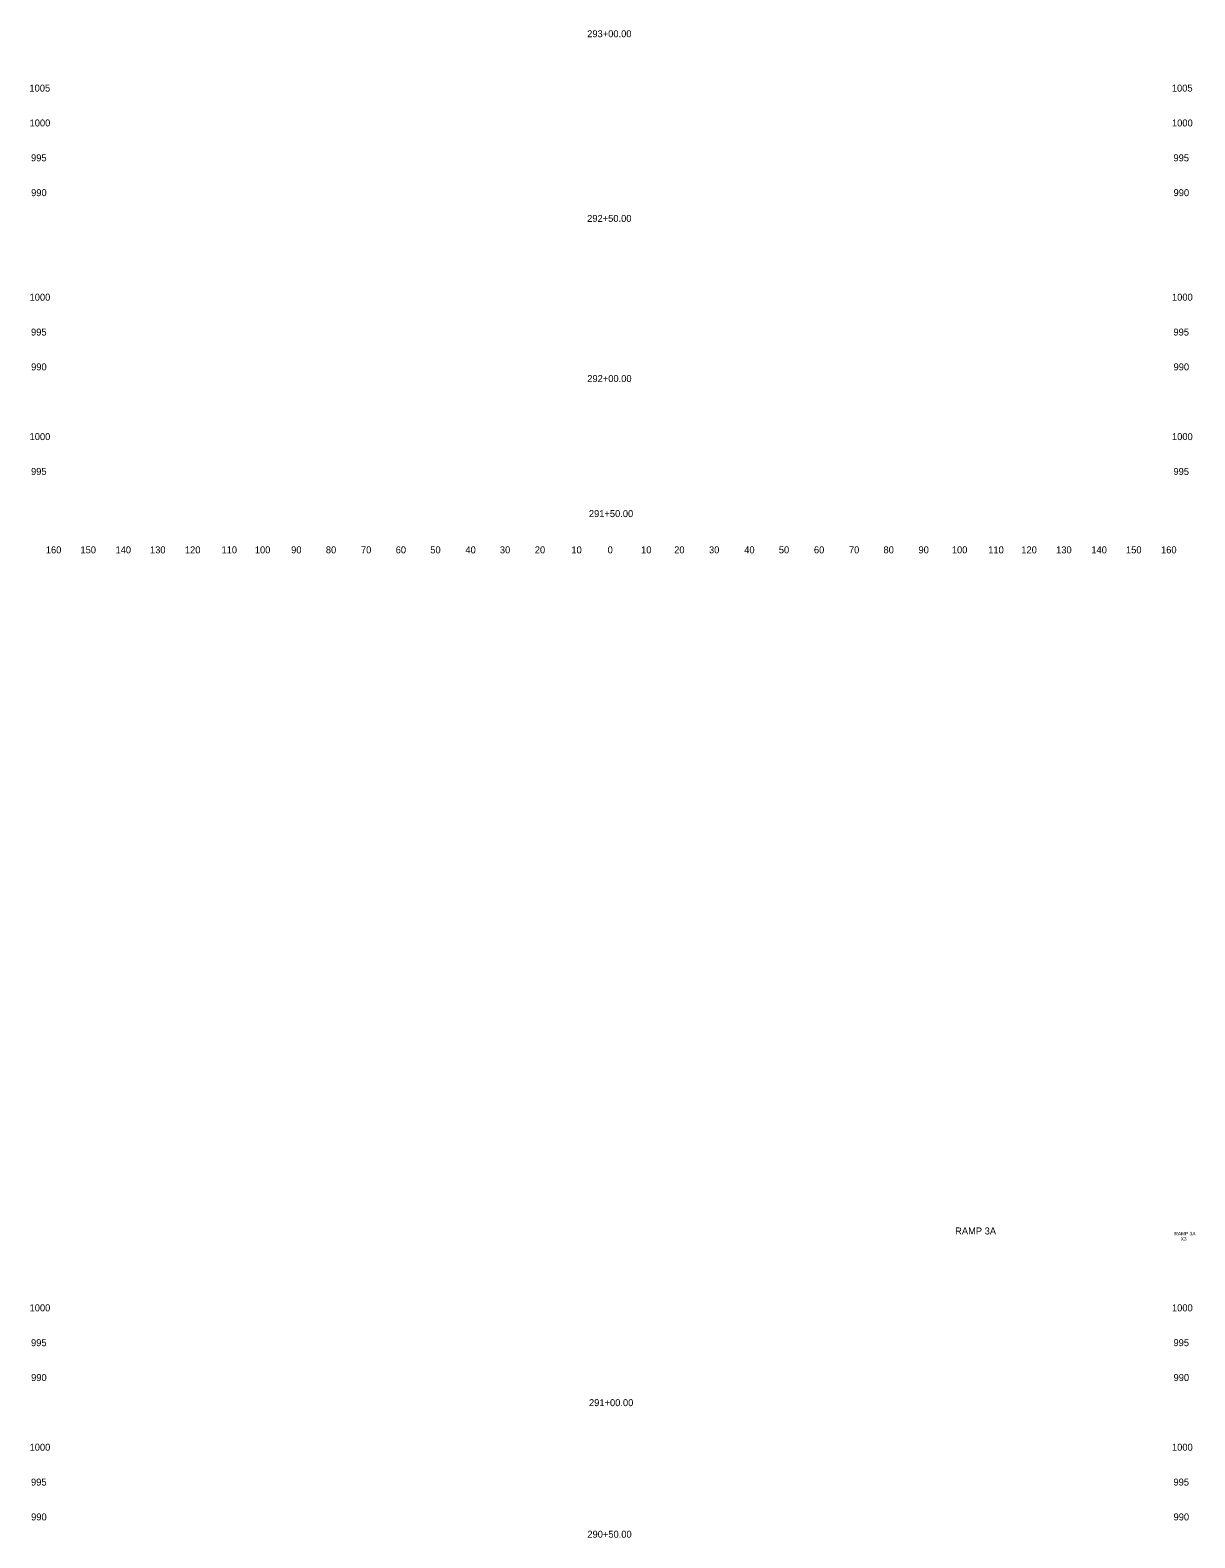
# Model space of a CAD drawing. Extents: x 4286 to 5843, y 4997 to 8804.
# Drawn here: x 4993.6 to 5327.8, y 5915 to 6347.6 of the extents above; entities that cross this region are included whole.
import ezdxf

# ---------------------------------------------------------------- set-up
doc = ezdxf.new("R2010")
doc.units = 0
for name, color, linetype in [('RD_SHT_ID', 7, 'Continuous'), ('RD_XS_TX_Offset', 7, 'Continuous'), ('RD_XS_TX_Station', 7, 'Continuous')]:
    doc.layers.add(name, color=color, linetype=linetype)

msp = doc.modelspace()

# ---------------------------------------------------------------- texts
at = {"layer": 'RD_SHT_ID'}
for s, height, p in [('RAMP 3A', 2, (5259.02, 6002.06)), ('RAMP 3A', 1, (5321.93, 6001.8)), ('X3', 1, (5323.74, 6000.3))]:
    msp.add_text(s, height=height, dxfattribs=at).set_placement(p)
at = {"layer": 'RD_XS_TX_Offset'}
for s, p in [('1005', (4993.4, 6330)), ('1005', (5321.2, 6330)), ('1000', (4993.44, 6320)), ('1000', (5321.24, 6320)), ('995', (4993.86, 6310)), ('995', (5321.66, 6310)), ('990', (4993.89, 6300)), ('990', (5321.69, 6300)), ('1000', (4993.44, 6270)), ('1000', (5321.24, 6270)), ('995', (4993.86, 6260)), ('995', (5321.66, 6260)), ('990', (4993.89, 6250)), ('990', (5321.69, 6250)), ('1000', (4993.44, 6230)), ('1000', (5321.24, 6230)), ('995', (4993.86, 6220)), ('995', (5321.66, 6220)), ('160', (4998.1, 6197.5)), ('150', (5008.04, 6197.5)), ('140', (5018.1, 6197.5)), ('130', (5027.99, 6197.5)), ('120', (5038.01, 6197.5)), ('110', (5048.51, 6197.5)), ('100', (5058.07, 6197.5)), ('90', (5068.5, 6197.5)), ('80', (5078.46, 6197.5)), ('70', (5088.54, 6197.5)), ('60', (5098.5, 6197.5)), ('50', (5108.43, 6197.5)), ('40', (5118.5, 6197.5)), ('30', (5128.39, 6197.5)), ('20', (5138.4, 6197.5)), ('10', (5148.91, 6197.5)), ('0', (5159.3, 6197.5)), ('0', (5159.3, 6197.5)), ('10', (5168.91, 6197.5)), ('20', (5178.4, 6197.5)), ('30', (5188.39, 6197.5)), ('40', (5198.5, 6197.5)), ('50', (5208.43, 6197.5)), ('60', (5218.5, 6197.5)), ('70', (5228.54, 6197.5)), ('80', (5238.46, 6197.5)), ('90', (5248.5, 6197.5)), ('100', (5258.07, 6197.5)), ('110', (5268.51, 6197.5)), ('120', (5278.01, 6197.5)), ('130', (5287.99, 6197.5)), ('140', (5298.1, 6197.5)), ('150', (5308.04, 6197.5)), ('160', (5318.1, 6197.5)), ('1000', (4993.44, 5980)), ('1000', (5321.24, 5980)), ('995', (4993.86, 5970)), ('995', (5321.66, 5970)), ('990', (4993.89, 5960)), ('990', (5321.69, 5960)), ('1000', (4993.44, 5940)), ('1000', (5321.24, 5940)), ('995', (4993.86, 5930)), ('995', (5321.66, 5930)), ('990', (4993.89, 5920)), ('990', (5321.69, 5920))]:
    msp.add_text(s, height=2, dxfattribs=at).set_placement(p)
at = {"layer": 'RD_XS_TX_Station'}
for s, p in [('293+00.00', (5153.44, 6345.6)), ('292+50.00', (5153.43, 6292.61)), ('292+00.00', (5153.46, 6246.65)), ('291+50.00', (5153.93, 6207.9)), ('291+00.00', (5153.96, 5952.79)), ('290+50.00', (5153.49, 5915.03))]:
    msp.add_text(s, height=2, dxfattribs=at).set_placement(p)

doc.saveas('drawing.dxf')
